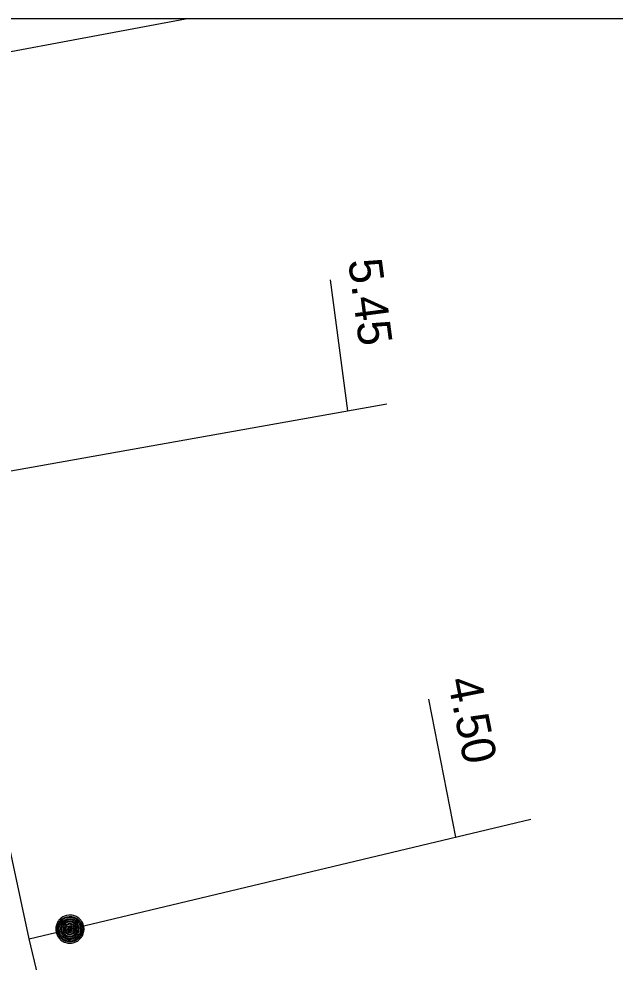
# Model space of a CAD drawing. Extents: x -820257 to -819974, y -1070894 to -1070484.
# Drawn here: x -820206.79 to -820185.49, y -1070518.08 to -1070484.4 of the extents above; entities that cross this region are included whole.
import ezdxf

# ---------------------------------------------------------------- set-up
doc = ezdxf.new("R2010")
doc.units = 0
for name, color, linetype in [('Default', 7, 'Continuous'), ('Oměrka vodovodu', 7, 'Continuous'), ('Oměrka-text', 7, 'Continuous'), ('Přípojka vodovodu', 7, 'Continuous'), ('Přípojkový uzávěr', 7, 'Continuous'), ('Roz-řad', 7, 'Continuous')]:
    doc.layers.add(name, color=color, linetype=linetype)

msp = doc.modelspace()

# ---------------------------------------------------------------- linework, layer by layer
at = {"layer": 'Default'}
msp.add_lwpolyline([(-819975.603, -1070484.403), (-820256.81, -1070484.403), (-820256.81, -1070893.932)], dxfattribs=at)
at = {"layer": 'Oměrka vodovodu'}
for p, q in [((-820195.039, -1070498.399), (-820195.654, -1070493.724)), ((-820191.183, -1070513.616), (-820192.15, -1070508.689))]:
    msp.add_line(p, q, dxfattribs=at)
at = {"layer": 'Přípojka vodovodu'}
for points in [[(-820212.767, -1070486.628), (-820211.291, -1070486.353), (-820200.838, -1070484.403)], [(-820209.898, -1070501.039), (-820208.421, -1070500.777), (-820193.65, -1070498.152)], [(-820206.422, -1070517.249), (-820204.963, -1070516.901), (-820188.499, -1070512.976)]]:
    msp.add_lwpolyline(points, dxfattribs=at)
at = {"layer": 'Přípojkový uzávěr'}
for points in [[(-820205.08, -1070516.414), (-820204.957, -1070516.385), (-820204.826, -1070516.42), (-820204.695, -1070516.455), (-820204.601, -1070516.557), (-820204.507, -1070516.658), (-820204.477, -1070516.785), (-820204.447, -1070516.912), (-820204.484, -1070517.042), (-820204.52, -1070517.173), (-820204.621, -1070517.265), (-820204.721, -1070517.357), (-820204.848, -1070517.387), (-820204.974, -1070517.417), (-820205.105, -1070517.381), (-820205.236, -1070517.344), (-820205.328, -1070517.244), (-820205.42, -1070517.143), (-820205.45, -1070517.017), (-820205.48, -1070516.89), (-820205.443, -1070516.757), (-820205.405, -1070516.625), (-820205.304, -1070516.534), (-820205.203, -1070516.444), (-820205.08, -1070516.414)], [(-820205.069, -1070516.46), (-820205.18, -1070516.487), (-820205.272, -1070516.568), (-820205.364, -1070516.65), (-820205.398, -1070516.771), (-820205.432, -1070516.891), (-820205.404, -1070517.006), (-820205.377, -1070517.121), (-820205.294, -1070517.212), (-820205.211, -1070517.303), (-820205.092, -1070517.336), (-820204.973, -1070517.369), (-820204.859, -1070517.342), (-820204.744, -1070517.314), (-820204.653, -1070517.231), (-820204.561, -1070517.148), (-820204.528, -1070517.029), (-820204.495, -1070516.911), (-820204.523, -1070516.796), (-820204.55, -1070516.681), (-820204.635, -1070516.589), (-820204.721, -1070516.497), (-820204.839, -1070516.465), (-820204.958, -1070516.434), (-820205.069, -1070516.46)], [(-820205.061, -1070516.493), (-820204.958, -1070516.469), (-820204.849, -1070516.498), (-820204.739, -1070516.527), (-820204.66, -1070516.612), (-820204.581, -1070516.697), (-820204.556, -1070516.804), (-820204.531, -1070516.91), (-820204.561, -1070517.02), (-820204.591, -1070517.129), (-820204.676, -1070517.206), (-820204.761, -1070517.283), (-820204.867, -1070517.308), (-820204.972, -1070517.333), (-820205.083, -1070517.303), (-820205.193, -1070517.273), (-820205.269, -1070517.188), (-820205.346, -1070517.104), (-820205.371, -1070516.998), (-820205.396, -1070516.891), (-820205.365, -1070516.78), (-820205.334, -1070516.669), (-820205.249, -1070516.593), (-820205.164, -1070516.518), (-820205.061, -1070516.493)], [(-820205.052, -1070516.536), (-820205.203, -1070516.572), (-820205.284, -1070516.704), (-820205.364, -1070516.837), (-820205.328, -1070516.988), (-820205.292, -1070517.139), (-820205.16, -1070517.22), (-820205.028, -1070517.301), (-820204.878, -1070517.266), (-820204.726, -1070517.229), (-820204.644, -1070517.097), (-820204.563, -1070516.965), (-820204.599, -1070516.814), (-820204.635, -1070516.663), (-820204.766, -1070516.581), (-820204.898, -1070516.5), (-820205.052, -1070516.536)], [(-820205.041, -1070516.581), (-820204.907, -1070516.549), (-820204.792, -1070516.62), (-820204.677, -1070516.691), (-820204.646, -1070516.824), (-820204.614, -1070516.956), (-820204.685, -1070517.072), (-820204.756, -1070517.188), (-820204.889, -1070517.219), (-820205.022, -1070517.251), (-820205.137, -1070517.18), (-820205.252, -1070517.109), (-820205.284, -1070516.976), (-820205.316, -1070516.844), (-820205.245, -1070516.728), (-820205.174, -1070516.612), (-820205.041, -1070516.581)], [(-820205.032, -1070516.619), (-820205.149, -1070516.647), (-820205.211, -1070516.749), (-820205.273, -1070516.851), (-820205.245, -1070516.967), (-820205.218, -1070517.083), (-820205.116, -1070517.146), (-820205.015, -1070517.209), (-820204.898, -1070517.181), (-820204.781, -1070517.153), (-820204.719, -1070517.051), (-820204.656, -1070516.949), (-820204.684, -1070516.833), (-820204.712, -1070516.717), (-820204.813, -1070516.654), (-820204.914, -1070516.591), (-820205.032, -1070516.619)], [(-820205.022, -1070516.658), (-820204.92, -1070516.633), (-820204.832, -1070516.688), (-820204.744, -1070516.742), (-820204.72, -1070516.843), (-820204.696, -1070516.944), (-820204.751, -1070517.032), (-820204.805, -1070517.12), (-820204.906, -1070517.144), (-820205.006, -1070517.168), (-820205.094, -1070517.114), (-820205.183, -1070517.06), (-820205.207, -1070516.959), (-820205.231, -1070516.858), (-820205.177, -1070516.77), (-820205.124, -1070516.682), (-820205.022, -1070516.658)], [(-820205.011, -1070516.703), (-820205.093, -1070516.722), (-820205.137, -1070516.794), (-820205.181, -1070516.865), (-820205.162, -1070516.947), (-820205.142, -1070517.03), (-820205.071, -1070517.074), (-820204.999, -1070517.117), (-820204.917, -1070517.098), (-820204.835, -1070517.078), (-820204.791, -1070517.007), (-820204.747, -1070516.935), (-820204.767, -1070516.853), (-820204.786, -1070516.771), (-820204.858, -1070516.727), (-820204.929, -1070516.683), (-820205.011, -1070516.703)], [(-820205.003, -1070516.736), (-820204.935, -1070516.72), (-820204.876, -1070516.757), (-820204.817, -1070516.793), (-820204.8, -1070516.861), (-820204.784, -1070516.93), (-820204.821, -1070516.989), (-820204.857, -1070517.048), (-820204.925, -1070517.064), (-820204.994, -1070517.08), (-820205.053, -1070517.044), (-820205.112, -1070517.008), (-820205.128, -1070516.939), (-820205.144, -1070516.871), (-820205.108, -1070516.812), (-820205.072, -1070516.753), (-820205.003, -1070516.736)], [(-820204.993, -1070516.779), (-820205.043, -1070516.791), (-820205.07, -1070516.835), (-820205.097, -1070516.879), (-820205.085, -1070516.93), (-820205.073, -1070516.98), (-820205.029, -1070517.007), (-820204.985, -1070517.034), (-820204.935, -1070517.022), (-820204.884, -1070517.01), (-820204.857, -1070516.966), (-820204.83, -1070516.922), (-820204.842, -1070516.872), (-820204.854, -1070516.821), (-820204.898, -1070516.794), (-820204.942, -1070516.767), (-820204.993, -1070516.779)], [(-820204.982, -1070516.825), (-820204.95, -1070516.817), (-820204.923, -1070516.834), (-820204.896, -1070516.85), (-820204.888, -1070516.883), (-820204.881, -1070516.914), (-820204.897, -1070516.942), (-820204.914, -1070516.969), (-820204.946, -1070516.977), (-820204.977, -1070516.984), (-820205.005, -1070516.967), (-820205.033, -1070516.95), (-820205.04, -1070516.919), (-820205.048, -1070516.887), (-820205.031, -1070516.859), (-820205.014, -1070516.832), (-820204.982, -1070516.825)], [(-820204.975, -1070516.855), (-820204.994, -1070516.86), (-820205.004, -1070516.876), (-820205.014, -1070516.892), (-820205.01, -1070516.912), (-820205.005, -1070516.931), (-820204.989, -1070516.941), (-820204.972, -1070516.951), (-820204.953, -1070516.946), (-820204.934, -1070516.942), (-820204.924, -1070516.925), (-820204.914, -1070516.909), (-820204.918, -1070516.89), (-820204.923, -1070516.87), (-820204.939, -1070516.861), (-820204.955, -1070516.851), (-820204.975, -1070516.855)]]:
    msp.add_open_spline(points, degree=3, dxfattribs=at)
at = {"layer": 'Roz-řad'}
msp.add_lwpolyline([(-820192.294, -1070583.934), (-820204.367, -1070525.825), (-820206.422, -1070517.249), (-820209.898, -1070501.039), (-820209.965, -1070500.833), (-820212.767, -1070486.628), (-820213.283, -1070484.403)], dxfattribs=at)

# ---------------------------------------------------------------- texts
at = {"layer": 'Oměrka-text'}
for s, rotation, p in [(' 5.45', 277.4943, (-820195.088, -1070492.589)), (' 4.50', 281.104, (-820191.564, -1070507.572))]:
    msp.add_text(s, height=1.2, rotation=rotation, dxfattribs=at).set_placement(p)

doc.saveas('drawing.dxf')
